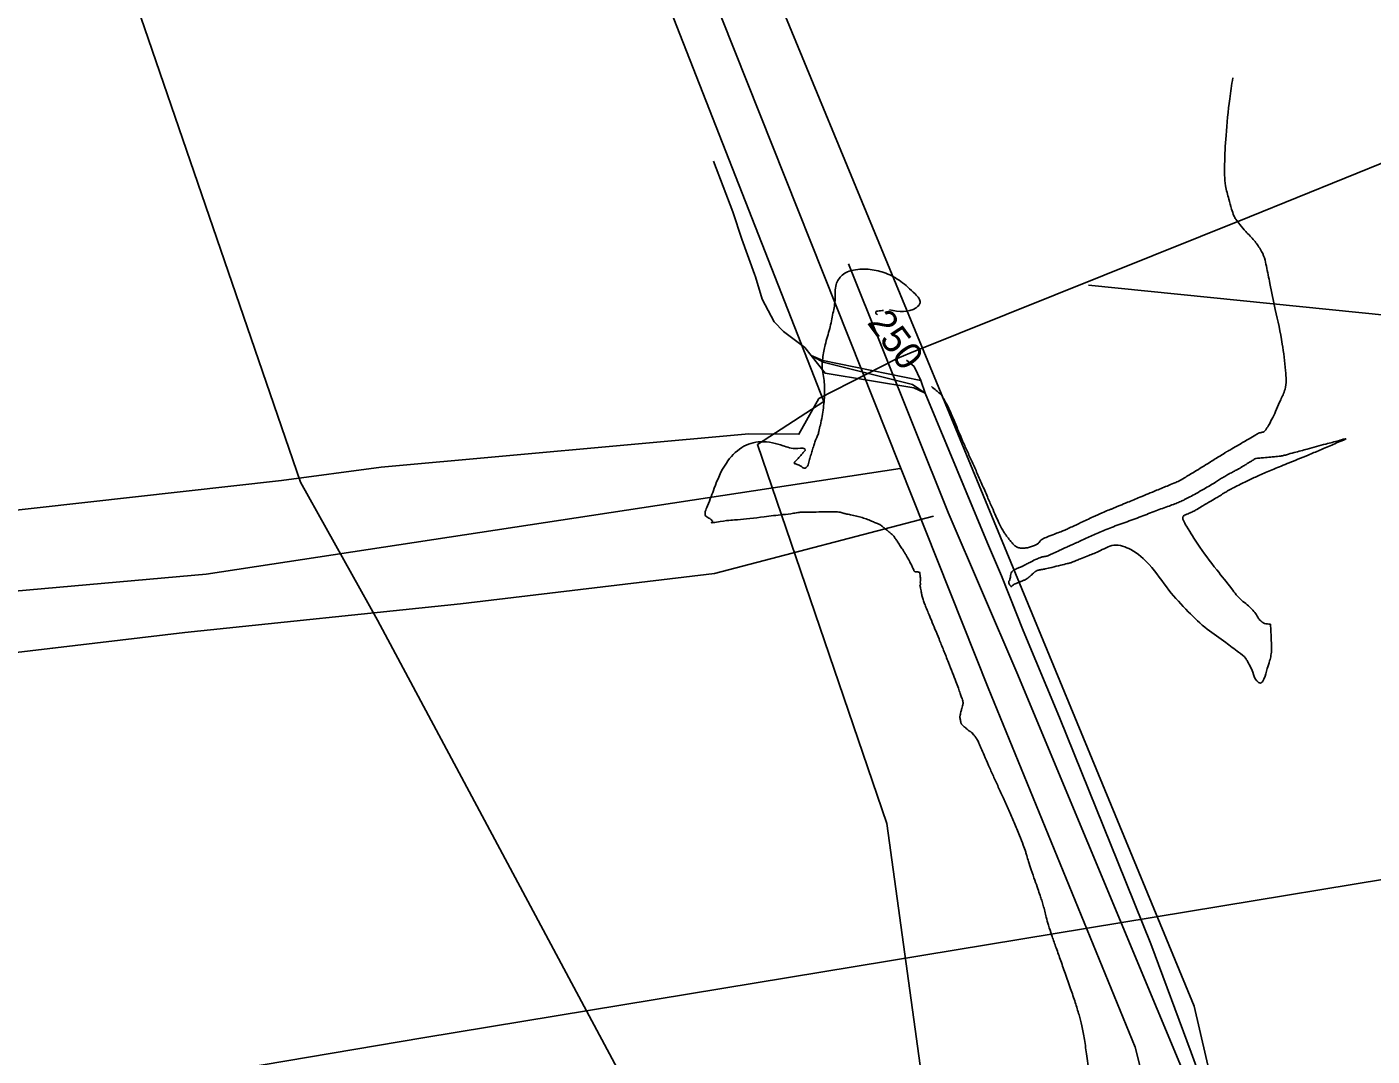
# Model space of a CAD drawing. Extents: x -478464 to -472469, y -1118040 to -1113785.
# Drawn here: x -476055.8 to -475861.1, y -1117262.5 to -1117113.6 of the extents above; entities that cross this region are included whole.
import ezdxf

# ---------------------------------------------------------------- set-up
doc = ezdxf.new("R2010")
doc.units = 0
for name, color, linetype in [('el vedeni _VN', 7, 'Continuous'), ('el vedeni_NN', 7, 'Continuous'), ('el vedeni_VVN', 7, 'Continuous'), ('ObPÚ', 7, 'Continuous'), ('plyn_vtl', 7, 'Continuous'), ('silnice', 7, 'Continuous'), ('telekomunikační kabel_O2', 7, 'Continuous'), ('VAK_vodovod', 7, 'Continuous'), ('Vrstevnice_hlavni', 7, 'Continuous'), ('Vrstevnice_popis', 7, 'Continuous')]:
    doc.layers.add(name, color=color, linetype=linetype)

msp = doc.modelspace()

# ---------------------------------------------------------------- linework, layer by layer
at = {"layer": 'el vedeni _VN'}
msp.add_lwpolyline([(-476054.13, -1117068.87), (-476016.19, -1117179.43), (-476005.061, -1117199.42), (-475940.421, -1117320.088)], dxfattribs=at)
at = {"layer": 'el vedeni_NN'}
for points in [[(-475936.884, -1117147.842), (-475922.455, -1117183.822), (-475912.509, -1117206.959)], [(-476142.527, -1117233.564), (-476143.465, -1117231.005), (-476140.291, -1117228.14), (-476109.493, -1117209.467), (-476071.248, -1117205.717), (-476032.928, -1117201.185), (-475993.047, -1117197.048), (-475956.253, -1117192.65), (-475924.554, -1117184.37)], [(-475912.509, -1117206.959), (-475881.908, -1117280.308), (-475845.463, -1117294.572), (-475796.905, -1117294.234), (-475790.107, -1117303.085)]]:
    msp.add_lwpolyline(points, dxfattribs=at)
at = {"layer": 'el vedeni_VVN'}
msp.add_lwpolyline([(-475278.421, -1117142.471), (-475502.649, -1117177.682), (-475743.53, -1117217.796), (-475998.47, -1117259.845), (-476243.025, -1117301.163), (-476469.01, -1117542.153)], dxfattribs=at)
at = {"layer": 'ObPÚ'}
msp.add_lwpolyline([(-475821.3, -1117143.22), (-475827.54, -1117139.09), (-475834.2, -1117137.62), (-475844.36, -1117127.07), (-475878.82, -1117141.03), (-475927.98, -1117160.79), (-475929.84, -1117161.54), (-475941.17, -1117167.34), (-475944.04, -1117172.5), (-475951.31, -1117172.43), (-476004.5, -1117177.28), (-476018.94, -1117179.19), (-476061.7, -1117183.99)], dxfattribs=at)
at = {"layer": 'plyn_vtl'}
msp.add_lwpolyline([(-475595.138, -1117298.191), (-475598.3, -1117295.92), (-475667.47, -1117237.33), (-475686.33, -1117221.12), (-475738.19, -1117171.6), (-475740.56, -1117170), (-475797.11, -1117162.8), (-475845.33, -1117156.66), (-475902.14, -1117150.95)], dxfattribs=at)
at = {"layer": 'silnice'}
for points in [[(-475903.982, -1117378.322), (-475889.519, -1117318.176), (-475888.389, -1117289.008), (-475895.395, -1117261.196), (-475916.638, -1117209.19), (-475969.886, -1117075.455), (-476021.05, -1116948.737), (-476052.923, -1116863.979), (-476081.44, -1116727.192), (-476114.99, -1116491.378), (-476128.411, -1116405.781), (-476137.637, -1116368.017), (-476162.8, -1116322.7), (-476200.543, -1116268.153), (-476239.965, -1116179.199), (-476260.934, -1116109.546), (-476288.613, -1116007.164), (-476289.451, -1115970.24), (-476274.354, -1115930.798), (-476261.922, -1115907.288), (-476366.595, -1115823.727)], [(-476424.073, -1117228.817), (-476282.324, -1117220.425), (-476211.029, -1117212.034), (-476121.67, -1117200.902), (-476029.858, -1117192.732), (-475929.409, -1117177.447)]]:
    msp.add_lwpolyline(points, dxfattribs=at)
at = {"layer": 'telekomunikační kabel_O2'}
for points in [[(-475967.4, -1117098.97), (-475940.43, -1117167.78), (-475950.06, -1117174), (-475931.33, -1117228.82), (-475924.1, -1117281.32), (-475911.23, -1117358.65), (-475927.92, -1117430.83), (-475926.17, -1117443.9), (-475937.75, -1117500.32), (-475940.1, -1117518.94), (-475929.72, -1117521.06), (-475934.27, -1117556.02), (-475935.89, -1117566.02), (-475936.969, -1117573.032)], [(-475953.59, -1117140.32), (-475956.42, -1117132.98)], [(-475950.5, -1117149.33), (-475952.3, -1117144.28), (-475953.59, -1117140.32)], [(-475942.29, -1117161.11), (-475943.19, -1117159.98), (-475946.28, -1117157.66), (-475947.65, -1117156.22), (-475949.35, -1117152.98), (-475950.35, -1117149.74), (-475950.5, -1117149.33)], [(-475925.77, -1117166.55), (-475927.6, -1117165.32), (-475940.53, -1117162.1), (-475942.29, -1117161.11)], [(-475925.77, -1117166.55), (-475927.41, -1117165.77), (-475940.26, -1117163.67), (-475942.29, -1117161.11)], [(-475941.28, -1117161.55), (-475942.29, -1117161.11)], [(-475926.38, -1117164.74), (-475940.58, -1117161.86), (-475941.28, -1117161.55)], [(-475928.5, -1117161.78), (-475927.37, -1117162.72), (-475926.38, -1117164.74)], [(-475926.38, -1117164.74), (-475925.77, -1117166.55)], [(-475912.112, -1117199.556), (-475914.73, -1117193.01), (-475916.77, -1117188.24), (-475925.77, -1117166.55)], [(-475923.355, -1117172.37), (-475916.77, -1117188.24), (-475914.73, -1117193.01), (-475911.57, -1117200.91), (-475906.35, -1117213.5), (-475897.84, -1117234.5), (-475893.13, -1117246.24), (-475887.26, -1117261.95), (-475881.63, -1117277.42), (-475880.27, -1117280.87), (-475878.41, -1117291.19), (-475878.66, -1117295.04), (-475878.84, -1117303.44), (-475879.2, -1117310.91), (-475879.17, -1117311.76)]]:
    msp.add_lwpolyline(points, dxfattribs=at)
at = {"layer": 'VAK_vodovod'}
msp.add_lwpolyline([(-475961.022, -1117076.006), (-475947.88, -1117107.78), (-475947.26, -1117108.989), (-475886.863, -1117255.251), (-475879.338, -1117287.714), (-475878.218, -1117296.341), (-475877.862, -1117316.562), (-475878.829, -1117320.819), (-475879.236, -1117324.31), (-475879.403, -1117324.54), (-475921.268, -1117487.378), (-475934.347, -1117574.649), (-475937.667, -1117596.666), (-475938.465, -1117600.746), (-475938.582, -1117601.233), (-475938.757, -1117601.897), (-475940.979, -1117601.583)], dxfattribs=at)
at = {"layer": 'Vrstevnice_hlavni'}
for points in [[(-475881.822, -1117138.488), (-475882.298, -1117136.547), (-475882.435, -1117133.482), (-475882.233, -1117129.293), (-475881.692, -1117123.979), (-475881.255, -1117120.961)], [(-475924.869, -1117165.582), (-475924.177, -1117166.164), (-475923.893, -1117166.407), (-475923.671, -1117166.602), (-475923.511, -1117166.749), (-475923.274, -1117167.084), (-475922.96, -1117167.608), (-475922.569, -1117168.319), (-475922.125, -1117169.249), (-475921.627, -1117170.396), (-475921.076, -1117171.761), (-475920.466, -1117173.201), (-475919.798, -1117174.717), (-475919.072, -1117176.307), (-475918.325, -1117177.977), (-475917.556, -1117179.725), (-475916.766, -1117181.553), (-475916.094, -1117183.094), (-475915.54, -1117184.347), (-475915.104, -1117185.312), (-475914.712, -1117186.097), (-475914.365, -1117186.7), (-475914.063, -1117187.123), (-475913.735, -1117187.557), (-475913.38, -1117188.002), (-475913, -1117188.458), (-475912.579, -1117188.775), (-475912.117, -1117188.951), (-475911.613, -1117188.986), (-475911.088, -1117188.941), (-475910.541, -1117188.813), (-475909.972, -1117188.605), (-475909.544, -1117188.384), (-475909.257, -1117188.152), (-475909.111, -1117187.908), (-475908.646, -1117187.607), (-475907.862, -1117187.25), (-475906.759, -1117186.836), (-475905.955, -1117186.527), (-475905.45, -1117186.324), (-475905.244, -1117186.226), (-475904.511, -1117185.883), (-475903.25, -1117185.295), (-475901.462, -1117184.461), (-475900.145, -1117183.861), (-475899.299, -1117183.496), (-475898.924, -1117183.367), (-475898.518, -1117183.211), (-475898.08, -1117183.03), (-475897.611, -1117182.823), (-475896.487, -1117182.352), (-475894.709, -1117181.617), (-475892.277, -1117180.618), (-475890.544, -1117179.904), (-475889.51, -1117179.475), (-475889.176, -1117179.331), (-475888.258, -1117178.808), (-475886.758, -1117177.905), (-475884.675, -1117176.622), (-475883.241, -1117175.734), (-475882.454, -1117175.242), (-475882.317, -1117175.146), (-475882.189, -1117175.064), (-475882.073, -1117174.997), (-475881.967, -1117174.944), (-475881.403, -1117174.622), (-475880.381, -1117174.03), (-475878.901, -1117173.169), (-475877.91, -1117172.594), (-475877.408, -1117172.306), (-475877.395, -1117172.303), (-475877.37, -1117172.3), (-475877.333, -1117172.298), (-475877.284, -1117172.296), (-475877.172, -1117172.269), (-475876.996, -1117172.219), (-475876.756, -1117172.145), (-475876.422, -1117171.763), (-475875.994, -1117171.074), (-475875.471, -1117170.078), (-475874.914, -1117168.901), (-475874.321, -1117167.542), (-475873.694, -1117166.003), (-475873.615, -1117163.305), (-475874.083, -1117159.45), (-475875.099, -1117154.435), (-475875.869, -1117150.689), (-475876.392, -1117148.211), (-475876.669, -1117147.001), (-475877.255, -1117145.76), (-475878.15, -1117144.488), (-475879.354, -1117143.187), (-475880.245, -1117142.157), (-475880.821, -1117141.4), (-475881.084, -1117140.914), (-475881.418, -1117139.944), (-475881.822, -1117138.488)], [(-475930.918, -1117154.529), (-475927.091, -1117154.196), (-475926.503, -1117153.48), (-475927.24, -1117152.214), (-475929.302, -1117150.397), (-475931.471, -1117149.215), (-475933.748, -1117148.667), (-475936.132, -1117148.753), (-475937.769, -1117149.482), (-475938.66, -1117150.856), (-475938.804, -1117152.873), (-475939.115, -1117154.995), (-475939.594, -1117157.22), (-475940.24, -1117159.55), (-475940.601, -1117161.482), (-475940.678, -1117163.016), (-475940.47, -1117164.152), (-475940.352, -1117165.284), (-475940.323, -1117166.413), (-475940.383, -1117167.539), (-475940.507, -1117168.708), (-475940.696, -1117169.92), (-475940.948, -1117171.176), (-475941.162, -1117172.102), (-475941.336, -1117172.697), (-475941.472, -1117172.962), (-475941.64, -1117173.385), (-475941.84, -1117173.966), (-475942.072, -1117174.704), (-475942.295, -1117175.442), (-475942.51, -1117176.178), (-475942.715, -1117176.914), (-475942.981, -1117177.326), (-475943.307, -1117177.413), (-475943.694, -1117177.176), (-475944.026, -1117176.997), (-475944.304, -1117176.874), (-475944.528, -1117176.808), (-475944.67, -1117176.742), (-475944.729, -1117176.675), (-475944.706, -1117176.609), (-475944.521, -1117176.383), (-475944.174, -1117175.997), (-475943.665, -1117175.452), (-475943.322, -1117175.07), (-475943.144, -1117174.851), (-475943.131, -1117174.794), (-475944.198, -1117174.565), (-475946.345, -1117174.163), (-475949.572, -1117173.588), (-475952.308, -1117174.424), (-475954.553, -1117176.67), (-475956.307, -1117180.326), (-475957.293, -1117182.884), (-475957.511, -1117184.344), (-475956.96, -1117184.706), (-475956.631, -1117184.974), (-475956.523, -1117185.148), (-475956.636, -1117185.228), (-475955.435, -1117185.138), (-475952.922, -1117184.878), (-475949.095, -1117184.447), (-475946.401, -1117184.135), (-475944.839, -1117183.942), (-475944.409, -1117183.867), (-475944.026, -1117183.817), (-475943.69, -1117183.791), (-475943.401, -1117183.789), (-475942.688, -1117183.78), (-475941.551, -1117183.761), (-475939.989, -1117183.735), (-475938.839, -1117183.747), (-475938.1, -1117183.797), (-475937.772, -1117183.886), (-475937.265, -1117184.007), (-475936.577, -1117184.16), (-475935.71, -1117184.344), (-475934.887, -1117184.569), (-475934.109, -1117184.835), (-475933.375, -1117185.14), (-475932.838, -1117185.366), (-475932.498, -1117185.513), (-475932.355, -1117185.581), (-475932.074, -1117185.779), (-475931.655, -1117186.106), (-475931.097, -1117186.562), (-475930.689, -1117186.908), (-475930.429, -1117187.143), (-475930.318, -1117187.267), (-475930.097, -1117187.576), (-475929.766, -1117188.071), (-475929.325, -1117188.751), (-475928.979, -1117189.287), (-475928.728, -1117189.677), (-475928.572, -1117189.922), (-475928.361, -1117190.294), (-475928.094, -1117190.794)], [(-475932.653, -1117155.22), (-475932.923, -1117154.883), (-475932.876, -1117154.759), (-475932.647, -1117154.679), (-475931.823, -1117154.607)], [(-475900.706, -1117186.785), (-475899.805, -1117186.392), (-475898.808, -1117185.988), (-475897.717, -1117185.575), (-475896.532, -1117185.153), (-475895.378, -1117184.731), (-475894.256, -1117184.308), (-475893.166, -1117183.885), (-475892.136, -1117183.495), (-475891.165, -1117183.136), (-475890.254, -1117182.81), (-475889.46, -1117182.504), (-475888.782, -1117182.22), (-475888.221, -1117181.958), (-475887.479, -1117181.575), (-475886.556, -1117181.073), (-475885.451, -1117180.451), (-475884.521, -1117179.91), (-475883.768, -1117179.45), (-475883.19, -1117179.071), (-475882.583, -1117178.7), (-475881.946, -1117178.336), (-475881.28, -1117177.98), (-475880.766, -1117177.703), (-475880.403, -1117177.507), (-475880.193, -1117177.39), (-475879.832, -1117177.175), (-475879.321, -1117176.862), (-475878.659, -1117176.449), (-475878.199, -1117176.17), (-475877.94, -1117176.025), (-475877.882, -1117176.013), (-475877.499, -1117175.973), (-475876.792, -1117175.905), (-475875.76, -1117175.809), (-475875.003, -1117175.737), (-475874.521, -1117175.688), (-475874.314, -1117175.663), (-475874.071, -1117175.617), (-475873.793, -1117175.551), (-475873.478, -1117175.465), (-475872.371, -1117175.165), (-475870.469, -1117174.652), (-475867.775, -1117173.924), (-475865.95, -1117173.435), (-475864.996, -1117173.184), (-475864.912, -1117173.172), (-475865.491, -1117173.438), (-475866.735, -1117173.982), (-475868.643, -1117174.805), (-475870.335, -1117175.522), (-475871.814, -1117176.133), (-475873.078, -1117176.639), (-475874.242, -1117177.11), (-475875.308, -1117177.545), (-475876.274, -1117177.946), (-475877.165, -1117178.329), (-475877.982, -1117178.695), (-475878.725, -1117179.044), (-475879.521, -1117179.431), (-475880.372, -1117179.858), (-475881.277, -1117180.323), (-475881.999, -1117180.711), (-475882.54, -1117181.02), (-475882.898, -1117181.252), (-475883.522, -1117181.635), (-475884.411, -1117182.169), (-475885.565, -1117182.855), (-475886.364, -1117183.326), (-475886.808, -1117183.582), (-475886.896, -1117183.624), (-475887.19, -1117183.764), (-475887.691, -1117184.002), (-475888.399, -1117184.338), (-475887.946, -1117185.807), (-475886.332, -1117188.408), (-475883.558, -1117192.141), (-475881.439, -1117194.845), (-475879.975, -1117196.521), (-475879.166, -1117197.167), (-475878.487, -1117197.821), (-475877.938, -1117198.482), (-475877.52, -1117199.151), (-475877.096, -1117199.613), (-475876.667, -1117199.869), (-475875.8, -1117199.969)], [(-475875.8, -1117199.969), (-475875.68, -1117202.403), (-475875.658, -1117203.359), (-475875.673, -1117204.054), (-475875.726, -1117204.488), (-475875.922, -1117205.276), (-475876.259, -1117206.418), (-475876.739, -1117207.915), (-475877.248, -1117208.499), (-475877.786, -1117208.171), (-475878.353, -1117206.931), (-475878.805, -1117205.979), (-475879.141, -1117205.316), (-475879.361, -1117204.941), (-475880.402, -1117204.046), (-475882.264, -1117202.632), (-475884.948, -1117200.698), (-475887.689, -1117198.176), (-475890.488, -1117195.066), (-475893.345, -1117191.367), (-475895.998, -1117189.203), (-475898.449, -1117188.572), (-475900.697, -1117189.475), (-475902.312, -1117190.127), (-475903.293, -1117190.526), (-475903.642, -1117190.674), (-475903.924, -1117190.79), (-475904.137, -1117190.873), (-475904.284, -1117190.925), (-475904.422, -1117190.977), (-475904.554, -1117191.031), (-475904.678, -1117191.085), (-475905.203, -1117191.224), (-475906.13, -1117191.449), (-475907.459, -1117191.76), (-475908.393, -1117191.972), (-475908.932, -1117192.087), (-475909.077, -1117192.105), (-475909.225, -1117192.131), (-475909.377, -1117192.167), (-475909.532, -1117192.212), (-475909.671, -1117192.27), (-475909.793, -1117192.34), (-475909.9, -1117192.424), (-475910.088, -1117192.585), (-475910.358, -1117192.824), (-475910.71, -1117193.139), (-475911.018, -1117193.381), (-475911.281, -1117193.547), (-475911.499, -1117193.639), (-475911.684, -1117193.715), (-475911.836, -1117193.776), (-475911.953, -1117193.823), (-475912.145, -1117193.899), (-475912.41, -1117194.007), (-475912.749, -1117194.146), (-475912.996, -1117194.272), (-475913.15, -1117194.387), (-475913.212, -1117194.49), (-475913.28, -1117194.535), (-475913.355, -1117194.521), (-475913.436, -1117194.45), (-475913.514, -1117194.346), (-475913.588, -1117194.21), (-475913.659, -1117194.043), (-475913.681, -1117193.9), (-475913.654, -1117193.781), (-475913.58, -1117193.687), (-475913.508, -1117193.483), (-475913.439, -1117193.17), (-475913.374, -1117192.747), (-475913.218, -1117192.413), (-475912.972, -1117192.166), (-475912.636, -1117192.007), (-475912.366, -1117191.886), (-475912.161, -1117191.802), (-475912.023, -1117191.756), (-475911.881, -1117191.697), (-475911.735, -1117191.623), (-475911.586, -1117191.536), (-475911.219, -1117191.345), (-475910.634, -1117191.049), (-475909.83, -1117190.648), (-475909.191, -1117190.371), (-475908.716, -1117190.217), (-475908.406, -1117190.187), (-475907.901, -1117190.024), (-475907.201, -1117189.727), (-475906.307, -1117189.297), (-475905.57, -1117188.951), (-475904.991, -1117188.688), (-475904.57, -1117188.508), (-475904.007, -1117188.261), (-475903.302, -1117187.946), (-475902.455, -1117187.563), (-475901.59, -1117187.176), (-475900.706, -1117186.785)], [(-475928.094, -1117190.794), (-475927.771, -1117191.421), (-475927.547, -1117191.876), (-475927.42, -1117192.158), (-475927.392, -1117192.268), (-475927.318, -1117192.345), (-475927.2, -1117192.388), (-475927.036, -1117192.399), (-475926.883, -1117192.418), (-475926.743, -1117192.446), (-475926.615, -1117192.482), (-475926.527, -1117192.705), (-475926.478, -1117193.114), (-475926.469, -1117193.711), (-475926.473, -1117194.117), (-475926.491, -1117194.334), (-475926.521, -1117194.361), (-475926.53, -1117194.407), (-475926.518, -1117194.472), (-475926.483, -1117194.555), (-475926.431, -1117194.79), (-475926.36, -1117195.176), (-475926.272, -1117195.712), (-475926.126, -1117196.282), (-475925.925, -1117196.884), (-475925.666, -1117197.52), (-475925.318, -1117198.365), (-475924.88, -1117199.422), (-475924.352, -1117200.688), (-475923.763, -1117202.127), (-475923.112, -1117203.739), (-475922.399, -1117205.524), (-475921.805, -1117207.037), (-475921.328, -1117208.278), (-475920.97, -1117209.247), (-475920.693, -1117210.011), (-475920.496, -1117210.569), (-475920.379, -1117210.921), (-475920.31, -1117211.202), (-475920.289, -1117211.41), (-475920.315, -1117211.546), (-475920.374, -1117211.801), (-475920.467, -1117212.174), (-475920.594, -1117212.666), (-475920.682, -1117213.023), (-475920.733, -1117213.246), (-475920.746, -1117213.334), (-475920.736, -1117213.492), (-475920.704, -1117213.718), (-475920.649, -1117214.013), (-475920.599, -1117214.235), (-475920.552, -1117214.384), (-475920.51, -1117214.46), (-475920.366, -1117214.609), (-475920.122, -1117214.83), (-475919.777, -1117215.123), (-475919.503, -1117215.343), (-475919.3, -1117215.489), (-475919.169, -1117215.562), (-475918.99, -1117215.724), (-475918.765, -1117215.973), (-475918.494, -1117216.31), (-475918.275, -1117216.627), (-475918.11, -1117216.924), (-475917.998, -1117217.199), (-475917.707, -1117217.875), (-475917.239, -1117218.951), (-475916.592, -1117220.428), (-475915.908, -1117221.958), (-475915.187, -1117223.541), (-475914.428, -1117225.177), (-475913.666, -1117226.891), (-475912.901, -1117228.682), (-475912.132, -1117230.55), (-475911.572, -1117231.97), (-475911.22, -1117232.944), (-475911.078, -1117233.47), (-475910.81, -1117234.327), (-475910.417, -1117235.517), (-475909.897, -1117237.038), (-475909.473, -1117238.279), (-475909.144, -1117239.239), (-475908.911, -1117239.919), (-475908.686, -1117240.672), (-475908.471, -1117241.496), (-475908.263, -1117242.393), (-475907.931, -1117243.542), (-475907.474, -1117244.942), (-475906.892, -1117246.594), (-475906.238, -1117248.44), (-475905.515, -1117250.481), (-475904.72, -1117252.716), (-475904.051, -1117254.726), (-475903.508, -1117256.51), (-475903.092, -1117258.07), (-475902.721, -1117260.055), (-475902.398, -1117262.467)], [(-476090.423, -1117262.79), (-476083.474, -1117249.454), (-476080.106, -1117246.497), (-476076.843, -1117247.249), (-476073.686, -1117251.712), (-476070.615, -1117256.041), (-476067.63, -1117260.234), (-476064.731, -1117264.293), (-476062.606, -1117267.264), (-476061.255, -1117269.149), (-476060.678, -1117269.946), (-476058.499, -1117271.151), (-476054.719, -1117272.763), (-476049.338, -1117274.782), (-476045.003, -1117276.657), (-476041.713, -1117278.387), (-476039.469, -1117279.973), (-476035.812, -1117282.094), (-476030.743, -1117284.749), (-476024.26, -1117287.938), (-476019.593, -1117291.643), (-476016.741, -1117295.864), (-476015.705, -1117300.6), (-476014.893, -1117303.818), (-476014.307, -1117305.517), (-476013.946, -1117305.699), (-476013.413, -1117306.032), (-476012.709, -1117306.516), (-476011.835, -1117307.151), (-476011.205, -1117307.522), (-476010.82, -1117307.628), (-476010.68, -1117307.469), (-476010.532, -1117307.337), (-476010.376, -1117307.23), (-476010.212, -1117307.149), (-476010.007, -1117307.098), (-476009.761, -1117307.076), (-476009.473, -1117307.084), (-476008.834, -1117305.974), (-476007.843, -1117303.746), (-476006.501, -1117300.4), (-476001.994, -1117298.311), (-475994.323, -1117297.479), (-475983.488, -1117297.905), (-475976.137, -1117298.157), (-475972.27, -1117298.236), (-475971.887, -1117298.141), (-475971.562, -1117298.096), (-475971.294, -1117298.099), (-475971.083, -1117298.151), (-475971.138, -1117298.702), (-475971.46, -1117299.752), (-475972.048, -1117301.302), (-475971.575, -1117304.216), (-475970.039, -1117308.495), (-475967.441, -1117314.138), (-475965.687, -1117317.94), (-475964.776, -1117319.9), (-475964.708, -1117320.019), (-475964.722, -1117320.406), (-475964.818, -1117321.061), (-475964.996, -1117321.985), (-475964.878, -1117322.934), (-475964.465, -1117323.909), (-475963.756, -1117324.909), (-475962.45, -1117325.507), (-475960.544, -1117325.703), (-475958.041, -1117325.497), (-475952.863, -1117325.106), (-475945.012, -1117324.53), (-475934.488, -1117323.77), (-475927.002, -1117323.054), (-475922.556, -1117322.382), (-475921.148, -1117321.754), (-475920.173, -1117321.309), (-475919.628, -1117321.047), (-475919.516, -1117320.967), (-475919.421, -1117320.897), (-475919.344, -1117320.835), (-475919.225, -1117320.732)], [(-475902.398, -1117262.467), (-475902.121, -1117265.304), (-475902.44, -1117267.705), (-475903.355, -1117269.67), (-475904.867, -1117271.199), (-475906.172, -1117273.366), (-475907.271, -1117276.171), (-475908.163, -1117279.614), (-475908.632, -1117282.335), (-475908.679, -1117284.333), (-475908.302, -1117285.609), (-475907.517, -1117287.571), (-475906.323, -1117290.218), (-475904.721, -1117293.552), (-475904.45, -1117297.38), (-475905.51, -1117301.704), (-475910.292, -1117311.342)]]:
    msp.add_spline(points, degree=3, dxfattribs=at)

# ---------------------------------------------------------------- texts
at = {"layer": 'Vrstevnice_popis'}
msp.add_text(' 250 ', height=4, rotation=306.44995, dxfattribs=at).set_placement((-475935.162, -1117155.18))

doc.saveas('drawing.dxf')
